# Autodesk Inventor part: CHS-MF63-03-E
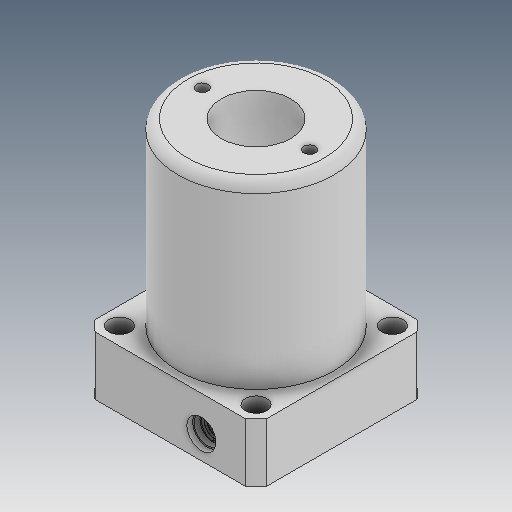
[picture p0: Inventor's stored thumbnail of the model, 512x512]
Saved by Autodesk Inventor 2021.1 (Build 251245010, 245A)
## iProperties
Created: 2019-05
Part Number: CHS-MF63-03-E
Material: Ogólny
Document SubType Name: Modeling
Designer: user
Density: 1 g/cm^3
Appearance: Domyślna
Author: user
Revision Number: ÈÎºÎ
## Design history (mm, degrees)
feature "ÊäÈë1"
node "Bryła1"
